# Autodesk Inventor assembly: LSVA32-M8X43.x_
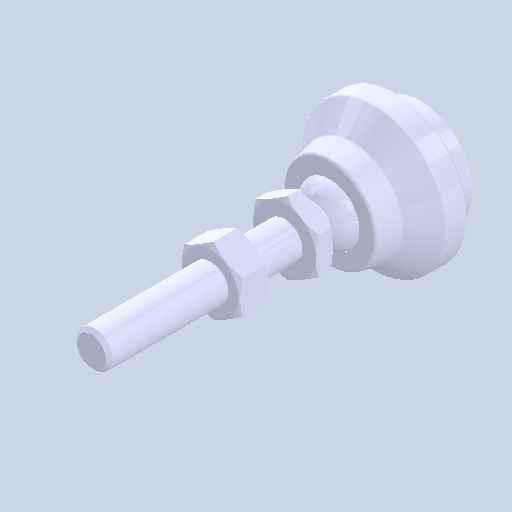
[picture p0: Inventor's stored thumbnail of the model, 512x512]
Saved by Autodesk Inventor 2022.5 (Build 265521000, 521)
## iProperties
Created: 2024-08
Part Number: LSVA32-M8X43.x_
Document SubType Name: Assembly
Designer: ImaoCorp
Author: ImaoCorp
Sending System: SOLIDWORKS 2022-2022290
MC: AMD64
MC_MODEL: Intel64 Family 6 Model 60 Stepping 3, GenuineIntel
OS: Windows_NT
FRU: Parasolid Version 33.1, build 260,  4-25-2022
FORMAT: text
GUISE: transmit
KEY: FILELSVA32-M8X43.x_t
DATE: Fri Aug 23 16:07:03 2024
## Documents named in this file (4)
- X:\14_SW2022-Inv2022\06_2024-10新製品(SME)\ELS_データ\l\lsva32-m8x43\LSVA32-M8X43.x_.iam
- X:\14_SW2022-Inv2022\06_2024-10新製品(SME)\ELS_データ\l\lsva32-m8x43\LSVA32-M8X43_01.ipt
- X:\14_SW2022-Inv2022\06_2024-10新製品(SME)\ELS_データ\l\lsva32-m8x43\LSVA32-M8X43_02.ipt
- X:\14_SW2022-Inv2022\06_2024-10新製品(SME)\ELS_データ\l\lsva32-m8x43\LSVA32-M8X43_03.ipt
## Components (3 placed, 3 different names)
1. LSVA32-M8X43_01
2. LSVA32-M8X43_02
3. LSVA32-M8X43_03
